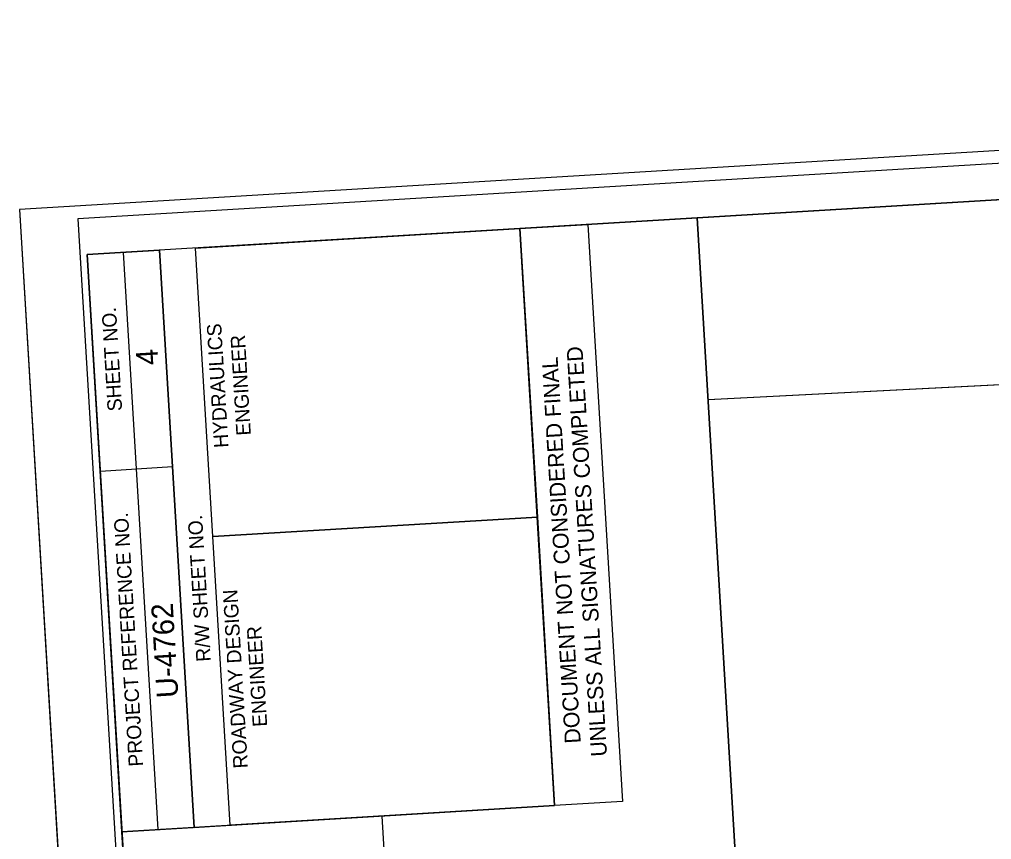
# Model space of a CAD drawing. Extents: x 2368361 to 2369555, y 800599 to 802345.
# Drawn here: x 2368361.2 to 2368697.7, y 802061.6 to 802345.4 of the extents above; entities that cross this region are included whole.
import ezdxf

# ---------------------------------------------------------------- set-up
doc = ezdxf.new("R2010")
doc.units = 0
for name, color, linetype in [('Default', 7, 'Continuous'), ('Old_Level_10', 7, 'Continuous'), ('Old_Level_15', 7, 'Continuous'), ('Old_Level_2', 7, 'Continuous'), ('Old_Level_4', 7, 'Continuous'), ('Old_Level_6', 7, 'Continuous'), ('Old_Level_61', 7, 'Continuous'), ('Plan Sheet CELL', 7, 'Continuous'), ('Plot Label CELL', 7, 'Continuous'), ('Plot Shape CELL', 7, 'Continuous')]:
    doc.layers.add(name, color=color, linetype=linetype)

msp = doc.modelspace()

# ---------------------------------------------------------------- linework, layer by layer
at = {"layer": 'Default'}
msp.add_line((2368599.6, 802213.8), (2369436.2, 802256.78), dxfattribs=at)
at = {"layer": 'Old_Level_10'}
for points in [[(2368474.82, 800766.64), (2369522.9, 800829.72), (2369432.81, 802327.02), (2368595.82, 802276.66), (2368610.18, 802037.84), (2368399.08, 802025.14)], [(2368610.18, 802037.84), (2368595.81, 802276.69), (2368384.71, 802264.01), (2368399.08, 802025.14)]]:
    msp.add_lwpolyline(points, close=True, dxfattribs=at)
at = {"layer": 'Old_Level_15'}
msp.add_line((2368361.24, 802279.59), (2368462.34, 800599.13), dxfattribs=at)
at = {"layer": 'Old_Level_2'}
msp.add_lwpolyline([(2368470.23, 800828.51), (2368399.08, 802025.14), (2368610.18, 802037.84), (2368599.6, 802213.8), (2369302.23, 802249.9), (2369298.05, 802318.92), (2369432.81, 802327.03), (2369518.34, 800891.57)], close=True, dxfattribs=at)
msp.add_lwpolyline([(2368470.23, 800828.51), (2368399.08, 802025.14), (2368610.18, 802037.84), (2368599.6, 802213.8), (2369302.23, 802249.9), (2369298.05, 802318.92), (2369432.81, 802327.03), (2369518.34, 800891.57)], close=True, dxfattribs=at)
at = {"layer": 'Old_Level_4'}
msp.add_lwpolyline([(2369534.62, 800676.67), (2369434.56, 802339.65), (2368381.48, 802276.3), (2368481.53, 800613.31)], close=True, dxfattribs=at)
at = {"layer": 'Old_Level_6'}
msp.add_lwpolyline([(2369555.37, 800664.89), (2369454.26, 802345.35), (2368361.24, 802279.59), (2368462.34, 800599.13)], close=True, dxfattribs=at)
at = {"layer": 'Old_Level_61'}
msp.add_lwpolyline([(2368396.71, 802064.28), (2368402.98, 801960.1), (2368493.03, 801965.52), (2368486.76, 802069.7)], close=True, dxfattribs=at)
at = {"layer": 'Plan Sheet CELL'}
for p, q in [((2368546.5, 802073.31), (2368534.49, 802272.98)), ((2368546.5, 802073.31), (2368534.49, 802272.98)), ((2368534.5, 802272.98), (2368557.96, 802274.4)), ((2368534.5, 802272.98), (2368557.96, 802274.4)), ((2368557.95, 802274.39), (2368569.96, 802074.72)), ((2368557.95, 802274.39), (2368569.96, 802074.72)), ((2368569.96, 802074.72), (2368546.5, 802073.31)), ((2368569.96, 802074.72), (2368546.5, 802073.31))]:
    msp.add_line(p, q, dxfattribs=at)
at = {"layer": 'Plot Shape CELL'}
for p, q in [((2368421.75, 802065.79), (2368409.71, 802265.46)), ((2368421.75, 802065.79), (2368409.71, 802265.46)), ((2368409.24, 802065.02), (2368397.24, 802264.71)), ((2368389.28, 802189.07), (2368414.23, 802190.63)), ((2368428.21, 802166.41), (2368540.47, 802173.17)), ((2368421.75, 802065.79), (2368434.22, 802066.54))]:
    msp.add_line(p, q, dxfattribs=at)
for points in [[(2368384.71, 802264), (2368474.79, 800766.67), (2369522.9, 800829.72), (2369432.81, 802327.03)], [(2369522.9, 800829.72), (2368474.82, 800766.64), (2368396.71, 802064.28), (2368546.5, 802073.31), (2368534.5, 802272.98), (2369432.81, 802327.03)], [(2368428.21, 802166.41), (2368422.19, 802266.21), (2368534.5, 802272.98), (2368540.52, 802173.17)], [(2368396.71, 802064.28), (2368384.71, 802264), (2368409.71, 802265.46), (2368421.75, 802065.79)], [(2368434.22, 802066.54), (2368428.21, 802166.41), (2368540.52, 802173.17), (2368546.5, 802073.31)]]:
    msp.add_lwpolyline(points, close=True, dxfattribs=at)

# ---------------------------------------------------------------- texts
at = {"layer": 'Plan Sheet CELL'}
for s, p in [('UNLESS ALL SIGNATURES COMPLETED', (2368564.65, 802090.43)), ('UNLESS ALL SIGNATURES COMPLETED', (2368564.65, 802090.43)), ('DOCUMENT NOT CONSIDERED FINAL', (2368555.56, 802094.96)), ('DOCUMENT NOT CONSIDERED FINAL', (2368555.56, 802094.96))]:
    msp.add_text(s, height=5.5, rotation=93.443, dxfattribs=at).set_placement(p)
at = {"layer": 'Plot Label CELL'}
for s, p in [('4', (2368409.29, 802225.93)), ('U-4762', (2368416.28, 802110.77))]:
    msp.add_text(s, height=7.5, rotation=93.443, dxfattribs=at).set_placement(p)
at = {"layer": 'Plot Shape CELL'}
for s, height, p in [('SHEET NO.', 5, (2368396.8, 802209.91)), ('HYDRAULICS', 5, (2368433.64, 802197.25)), ('ENGINEER', 5, (2368441.36, 802201.49)), ('PROJECT REFERENCE NO.', 5.0001, (2368404.09, 802086.97)), ('R/W SHEET NO.', 5.0001, (2368427.5, 802123.24)), ('ROADWAY DESIGN', 5.0001, (2368440.34, 802086.32)), ('ENGINEER', 5, (2368447.02, 802100.73))]:
    msp.add_text(s, height=height, rotation=93.443, dxfattribs=at).set_placement(p)

doc.saveas('drawing.dxf')
